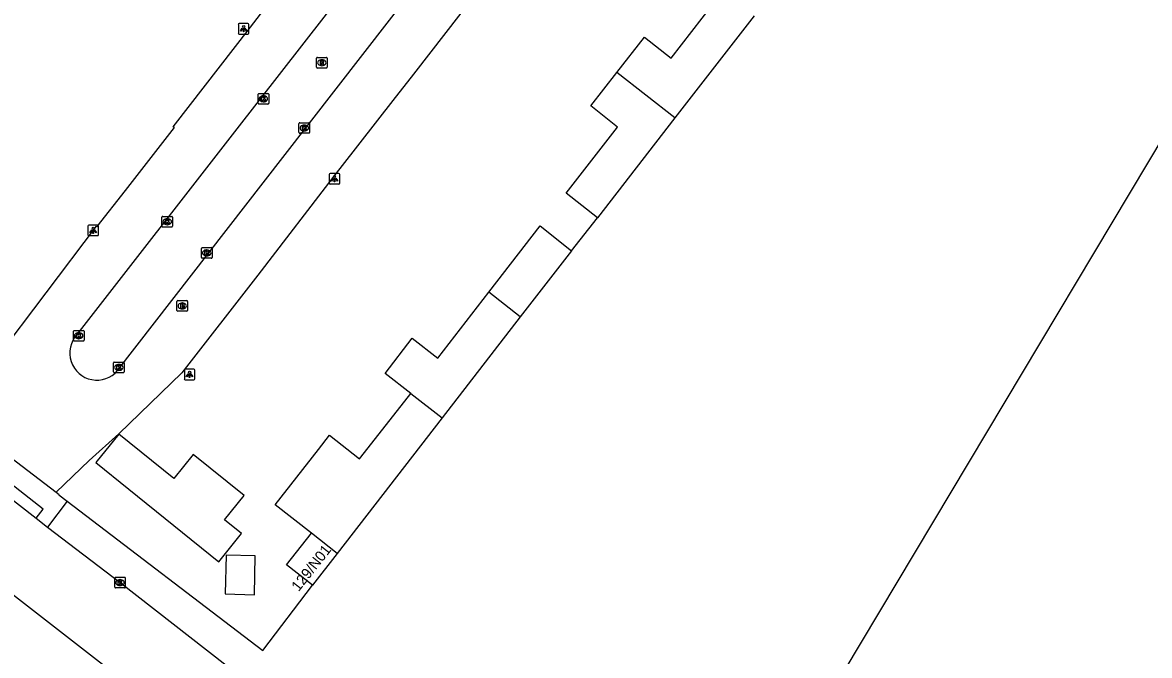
# Model space of a CAD drawing. Extents: x 159451 to 160663, y 388402 to 389723.
# Drawn here: x 160229.1 to 160335.5, y 389285.1 to 389344.8 of the extents above; entities that cross this region are included whole.
import ezdxf

# ---------------------------------------------------------------- set-up
doc = ezdxf.new("R2010")
doc.units = 0
for name, color, linetype in [('IMGEO_Brandkraan', 7, 'Continuous'), ('IMGEO_Groenvoorziening', 7, 'Continuous'), ('IMGEO_Kolk', 7, 'Continuous'), ('IMGEO_Lichtpunt', 7, 'Continuous'), ('IMGEO_Loofbos', 7, 'Continuous'), ('IMGEO_Pand', 7, 'Continuous'), ('IMGEO_Pand_nummerreeks', 7, 'Continuous'), ('IMGEO_Rijbaan_lokaal_gesloten', 7, 'Continuous'), ('IMGEO_Rijbaan_lokaal_open', 7, 'Continuous'), ('IMGEO_Rioolput', 7, 'Continuous')]:
    doc.layers.add(name, color=color, linetype=linetype)

msp = doc.modelspace()

# ---------------------------------------------------------------- linework, layer by layer
at = {"layer": 'IMGEO_Brandkraan'}
for p, q in [((160243.71, 389317.66), (160243.71, 389318.51)), ((160243.79, 389318.59), (160244.64, 389318.59)), ((160244.2, 389318.36), (160244.23, 389318.36)), ((160244.71, 389318.51), (160244.71, 389317.66)), ((160244.64, 389317.58), (160243.79, 389317.58)), ((160244.22, 389317.81), (160244.2, 389317.81))]:
    msp.add_line(p, q, dxfattribs=at)
for points in [[(160243.71, 389317.66), (160243.71, 389318.51)], [(160243.79, 389318.59), (160244.64, 389318.59)], [(160244.06, 389318.28), (160244.06, 389317.88), (160244.27, 389317.88)], [(160244.29, 389318.28), (160244.06, 389318.28)], [(160244.24, 389318.2), (160244.19, 389318.2), (160244.19, 389318.13)], [(160244.19, 389318.13), (160244.24, 389318.13)], [(160244.25, 389318.05), (160244.19, 389318.05), (160244.19, 389317.97)], [(160244.19, 389317.97), (160244.25, 389317.97)], [(160244.71, 389318.51), (160244.71, 389317.66)], [(160244.64, 389317.58), (160243.79, 389317.58)]]:
    msp.add_lwpolyline(points, dxfattribs=at)
for centre, radius, start, end in [((160243.79, 389318.51), 0.0765, 91.552, 178.448), ((160243.79, 389318.51), 0.0765, 91.552, 178.448), ((160244.24, 389318.17), 0.0379, 267.8285, 90.9355), ((160244.25, 389318.01), 0.0404, 269.8759, 90.5077), ((160244.28, 389318.14), 0.251, 268.6676, 293.5347), ((160244.3, 389318.14), 0.145, 59.4692, 91.5367), ((160244.32, 389318.19), 0.0922, 285.5137, 58.1501), ((160244.33, 389318), 0.105, 301.3115, 78.989), ((160244.64, 389318.51), 0.0765, 1.552, 88.448), ((160244.64, 389318.51), 0.0765, 1.552, 88.448), ((160243.79, 389317.66), 0.0765, 181.552, 268.448), ((160243.79, 389317.66), 0.0765, 181.552, 268.448), ((160244.64, 389317.66), 0.0765, 271.552, 358.448), ((160244.64, 389317.66), 0.0765, 271.552, 358.448)]:
    msp.add_arc(centre, radius, start, end, dxfattribs=at)
for centre, major_axis, ratio, start_param, end_param in [((160244.2, 389318.08), (-0.387, 0.002), 0.722429, 4.712389, 7.853982), ((160244.22, 389318.08), (-0.39, 0.002), 0.717154, 1.570796, 4.712389)]:
    msp.add_ellipse(centre, major_axis=major_axis, ratio=ratio, start_param=start_param, end_param=end_param, dxfattribs=at)
at = {"layer": 'IMGEO_Groenvoorziening'}
for points in [[(160280.95, 389323.29), (160283.42, 389326.4)], [(160233.35, 389299.67), (160251.82, 389285.59), (160256.51, 389291.74)]]:
    msp.add_lwpolyline(points, dxfattribs=at)
at = {"layer": 'IMGEO_Kolk'}
for p, q in [((160251.45, 389338.11), (160252.3, 389338.11)), ((160251.37, 389337.18), (160251.37, 389338.04)), ((160252.3, 389337.11), (160251.45, 389337.11)), ((160251.86, 389337.89), (160251.88, 389337.89)), ((160251.88, 389337.33), (160251.86, 389337.33)), ((160252.37, 389338.04), (160252.37, 389337.18)), ((160255.23, 389334.43), (160255.23, 389335.28)), ((160255.3, 389335.36), (160256.16, 389335.36)), ((160255.72, 389335.14), (160255.74, 389335.14)), ((160256.23, 389335.28), (160256.23, 389334.43)), ((160256.16, 389334.36), (160255.3, 389334.36)), ((160255.74, 389334.58), (160255.71, 389334.58)), ((160242.3, 389325.6), (160242.3, 389326.45)), ((160242.37, 389326.52), (160243.22, 389326.52)), ((160243.3, 389326.45), (160243.3, 389325.6)), ((160243.22, 389325.52), (160242.37, 389325.52)), ((160242.78, 389326.3), (160242.81, 389326.3)), ((160242.81, 389325.74), (160242.78, 389325.74)), ((160246.02, 389322.65), (160246.02, 389323.5)), ((160246.1, 389323.58), (160246.95, 389323.58)), ((160246.51, 389323.36), (160246.54, 389323.36)), ((160247.03, 389323.5), (160247.03, 389322.65)), ((160246.95, 389322.58), (160246.1, 389322.58)), ((160246.53, 389322.8), (160246.51, 389322.8)), ((160234.02, 389315.77), (160234.87, 389315.77)), ((160233.94, 389314.84), (160233.94, 389315.7)), ((160234.87, 389314.77), (160234.02, 389314.77)), ((160234.43, 389315.55), (160234.45, 389315.55)), ((160234.45, 389314.99), (160234.43, 389314.99)), ((160234.94, 389315.7), (160234.94, 389314.84)), ((160237.73, 389311.86), (160237.73, 389312.71)), ((160237.8, 389312.78), (160238.66, 389312.78)), ((160238.73, 389312.71), (160238.73, 389311.86)), ((160238.66, 389311.78), (160237.8, 389311.78)), ((160238.24, 389312), (160238.21, 389312)), ((160238.22, 389312.56), (160238.24, 389312.56)), ((160237.84, 389291.56), (160237.84, 389292.42)), ((160237.92, 389292.49), (160238.77, 389292.49)), ((160238.84, 389292.42), (160238.84, 389291.56)), ((160238.77, 389291.49), (160237.92, 389291.49)), ((160238.33, 389292.27), (160238.35, 389292.27)), ((160238.35, 389291.71), (160238.33, 389291.71))]:
    msp.add_line(p, q, dxfattribs=at)
for points in [[(160251.45, 389338.11), (160252.3, 389338.11)], [(160251.37, 389337.18), (160251.37, 389338.04)], [(160252.3, 389337.11), (160251.45, 389337.11)], [(160251.69, 389337.81), (160251.82, 389337.81), (160251.82, 389337.66), (160251.94, 389337.81), (160252.11, 389337.81), (160251.96, 389337.66), (160252.12, 389337.41), (160251.96, 389337.41), (160251.88, 389337.58), (160251.82, 389337.51), (160251.82, 389337.41), (160251.69, 389337.41), (160251.69, 389337.81)], [(160252.37, 389338.04), (160252.37, 389337.18)], [(160255.23, 389334.43), (160255.23, 389335.28)], [(160255.3, 389335.36), (160256.16, 389335.36)], [(160255.55, 389335.06), (160255.67, 389335.06), (160255.67, 389334.91), (160255.8, 389335.06), (160255.97, 389335.06), (160255.82, 389334.91), (160255.97, 389334.66), (160255.82, 389334.66), (160255.74, 389334.82), (160255.67, 389334.76), (160255.67, 389334.66), (160255.55, 389334.66), (160255.55, 389335.06)], [(160256.23, 389335.28), (160256.23, 389334.43)], [(160256.16, 389334.36), (160255.3, 389334.36)], [(160242.3, 389325.6), (160242.3, 389326.45)], [(160242.37, 389326.52), (160243.22, 389326.52)], [(160243.3, 389326.45), (160243.3, 389325.6)], [(160243.22, 389325.52), (160242.37, 389325.52)], [(160242.62, 389326.22), (160242.74, 389326.22), (160242.74, 389326.07), (160242.87, 389326.22), (160243.03, 389326.22), (160242.89, 389326.07), (160243.04, 389325.82), (160242.89, 389325.82), (160242.8, 389325.99), (160242.74, 389325.92), (160242.74, 389325.82), (160242.62, 389325.82), (160242.62, 389326.22)], [(160246.02, 389322.65), (160246.02, 389323.5)], [(160246.1, 389323.58), (160246.95, 389323.58)], [(160246.34, 389323.28), (160246.47, 389323.28), (160246.47, 389323.13), (160246.6, 389323.28), (160246.76, 389323.28), (160246.62, 389323.13), (160246.77, 389322.88), (160246.62, 389322.88), (160246.53, 389323.04), (160246.47, 389322.98), (160246.47, 389322.88), (160246.34, 389322.88), (160246.34, 389323.28)], [(160247.03, 389323.5), (160247.03, 389322.65)], [(160246.95, 389322.58), (160246.1, 389322.58)], [(160234.02, 389315.77), (160234.87, 389315.77)], [(160233.94, 389314.84), (160233.94, 389315.7)], [(160234.87, 389314.77), (160234.02, 389314.77)], [(160234.26, 389315.47), (160234.39, 389315.47), (160234.39, 389315.32), (160234.51, 389315.47), (160234.68, 389315.47), (160234.53, 389315.32), (160234.69, 389315.07), (160234.53, 389315.07), (160234.45, 389315.23), (160234.39, 389315.17), (160234.39, 389315.07), (160234.26, 389315.07), (160234.26, 389315.47)], [(160234.94, 389315.7), (160234.94, 389314.84)], [(160237.73, 389311.86), (160237.73, 389312.71)], [(160237.8, 389312.78), (160238.66, 389312.78)], [(160238.73, 389312.71), (160238.73, 389311.86)], [(160238.66, 389311.78), (160237.8, 389311.78)], [(160238.05, 389312.48), (160238.17, 389312.48), (160238.17, 389312.33), (160238.3, 389312.48), (160238.47, 389312.48), (160238.32, 389312.33), (160238.47, 389312.08), (160238.32, 389312.08), (160238.24, 389312.25), (160238.17, 389312.18), (160238.17, 389312.08), (160238.05, 389312.08), (160238.05, 389312.48)], [(160237.84, 389291.56), (160237.84, 389292.42)], [(160237.92, 389292.49), (160238.77, 389292.49)], [(160238.84, 389292.42), (160238.84, 389291.56)], [(160238.77, 389291.49), (160237.92, 389291.49)], [(160238.16, 389292.19), (160238.29, 389292.19), (160238.29, 389292.04), (160238.41, 389292.19), (160238.58, 389292.19), (160238.43, 389292.04), (160238.59, 389291.79), (160238.43, 389291.79), (160238.35, 389291.95), (160238.29, 389291.89), (160238.29, 389291.79), (160238.16, 389291.79), (160238.16, 389292.19)]]:
    msp.add_lwpolyline(points, dxfattribs=at)
for centre, start, end in [((160251.45, 389338.04), 91.552, 178.448), ((160251.45, 389338.04), 91.552, 178.448), ((160252.3, 389338.04), 1.552, 88.448), ((160252.3, 389338.04), 1.552, 88.448), ((160251.45, 389337.19), 181.552, 268.448), ((160251.45, 389337.19), 181.552, 268.448), ((160252.3, 389337.19), 271.552, 358.448), ((160252.3, 389337.19), 271.552, 358.448), ((160255.31, 389335.28), 91.552, 178.448), ((160255.31, 389335.28), 91.552, 178.448), ((160256.15, 389335.28), 1.552, 88.448), ((160256.15, 389335.28), 1.552, 88.448), ((160255.31, 389334.43), 181.552, 268.448), ((160255.31, 389334.43), 181.552, 268.448), ((160256.15, 389334.43), 271.552, 358.448), ((160256.15, 389334.43), 271.552, 358.448), ((160242.37, 389326.45), 91.552, 178.448), ((160242.37, 389326.45), 91.552, 178.448), ((160243.22, 389326.45), 1.552, 88.448), ((160243.22, 389326.45), 1.552, 88.448), ((160242.37, 389325.6), 181.552, 268.448), ((160242.37, 389325.6), 181.552, 268.448), ((160243.22, 389325.6), 271.552, 358.448), ((160243.22, 389325.6), 271.552, 358.448), ((160246.1, 389323.5), 91.552, 178.448), ((160246.1, 389323.5), 91.552, 178.448), ((160246.95, 389323.5), 1.552, 88.448), ((160246.95, 389323.5), 1.552, 88.448), ((160246.1, 389322.65), 181.552, 268.448), ((160246.1, 389322.65), 181.552, 268.448), ((160246.95, 389322.65), 271.552, 358.448), ((160246.95, 389322.65), 271.552, 358.448), ((160234.02, 389315.69), 91.552, 178.448), ((160234.02, 389315.69), 91.552, 178.448), ((160234.87, 389315.69), 1.552, 88.448), ((160234.87, 389315.69), 1.552, 88.448), ((160234.02, 389314.85), 181.552, 268.448), ((160234.02, 389314.85), 181.552, 268.448), ((160234.87, 389314.85), 271.552, 358.448), ((160234.87, 389314.85), 271.552, 358.448), ((160237.8, 389312.71), 91.552, 178.448), ((160237.8, 389312.71), 91.552, 178.448), ((160238.65, 389312.71), 1.552, 88.448), ((160238.65, 389312.71), 1.552, 88.448), ((160237.8, 389311.86), 181.552, 268.448), ((160237.8, 389311.86), 181.552, 268.448), ((160238.65, 389311.86), 271.552, 358.448), ((160238.65, 389311.86), 271.552, 358.448), ((160237.92, 389292.41), 91.552, 178.448), ((160237.92, 389292.41), 91.552, 178.448), ((160238.77, 389292.41), 1.552, 88.448), ((160238.77, 389292.41), 1.552, 88.448), ((160237.92, 389291.56), 181.552, 268.448), ((160237.92, 389291.56), 181.552, 268.448), ((160238.77, 389291.56), 271.552, 358.448), ((160238.77, 389291.56), 271.552, 358.448)]:
    msp.add_arc(centre, 0.0765, start, end, dxfattribs=at)
for centre, major_axis, ratio, start_param, end_param in [((160251.86, 389337.61), (-0.387, 0.002), 0.722429, 4.712389, 7.853982), ((160251.88, 389337.61), (-0.39, 0.002), 0.717154, 1.570796, 4.712389), ((160255.72, 389334.86), (-0.387, 0.002), 0.722429, 4.712389, 7.853982), ((160255.74, 389334.86), (-0.39, 0.002), 0.717154, 1.570796, 4.712389), ((160242.78, 389326.02), (-0.387, 0.002), 0.722429, 4.712389, 7.853982), ((160242.81, 389326.02), (-0.39, 0.002), 0.717154, 1.570796, 4.712389), ((160246.51, 389323.08), (-0.387, 0.002), 0.722429, 4.712389, 7.853982), ((160246.54, 389323.08), (-0.39, 0.002), 0.717154, 1.570796, 4.712389), ((160234.43, 389315.27), (-0.387, 0.002), 0.722429, 4.712389, 7.853982), ((160234.45, 389315.27), (-0.39, 0.002), 0.717154, 1.570796, 4.712389), ((160238.22, 389312.28), (-0.387, 0.002), 0.722429, 4.712389, 7.853982), ((160238.24, 389312.28), (-0.39, 0.002), 0.717154, 1.570796, 4.712389), ((160238.33, 389291.99), (-0.387, 0.002), 0.722429, 4.712389, 7.853982), ((160238.35, 389291.99), (-0.39, 0.002), 0.717154, 1.570796, 4.712389)]:
    msp.add_ellipse(centre, major_axis=major_axis, ratio=ratio, start_param=start_param, end_param=end_param, dxfattribs=at)
at = {"layer": 'IMGEO_Lichtpunt'}
for p, q in [((160249.51, 389344.62), (160249.51, 389343.81)), ((160249.51, 389344.62), (160249.51, 389343.81)), ((160250.41, 389344.71), (160249.6, 389344.71)), ((160250.41, 389344.71), (160249.6, 389344.71)), ((160250.51, 389343.81), (160250.51, 389344.62)), ((160250.51, 389343.81), (160250.51, 389344.62)), ((160249.6, 389343.72), (160250.41, 389343.72)), ((160249.6, 389343.72), (160250.41, 389343.72)), ((160258.09, 389330.48), (160258.09, 389329.67)), ((160258.09, 389330.48), (160258.09, 389329.67)), ((160258.99, 389330.57), (160258.18, 389330.57)), ((160258.99, 389330.57), (160258.18, 389330.57)), ((160259.09, 389329.67), (160259.09, 389330.48)), ((160259.09, 389329.67), (160259.09, 389330.48)), ((160258.18, 389329.58), (160258.99, 389329.58)), ((160258.18, 389329.58), (160258.99, 389329.58)), ((160235.31, 389325.61), (160235.31, 389324.8)), ((160235.31, 389325.61), (160235.31, 389324.8)), ((160236.21, 389325.71), (160235.4, 389325.71)), ((160236.21, 389325.71), (160235.4, 389325.71)), ((160236.3, 389324.8), (160236.3, 389325.61)), ((160236.3, 389324.8), (160236.3, 389325.61)), ((160235.4, 389324.71), (160236.21, 389324.71)), ((160235.4, 389324.71), (160236.21, 389324.71)), ((160244.41, 389312.03), (160244.41, 389311.22)), ((160244.41, 389312.03), (160244.41, 389311.22)), ((160245.31, 389312.12), (160244.5, 389312.12)), ((160245.31, 389312.12), (160244.5, 389312.12)), ((160245.4, 389311.22), (160245.4, 389312.03)), ((160245.4, 389311.22), (160245.4, 389312.03)), ((160244.5, 389311.12), (160245.31, 389311.12)), ((160244.5, 389311.12), (160245.31, 389311.12))]:
    msp.add_line(p, q, dxfattribs=at)
for points in [[(160249.88, 389344.28), (160249.92, 389344.25), (160249.74, 389343.99), (160249.7, 389344.02), (160249.88, 389344.28)], [(160249.99, 389344.23), (160250.03, 389344.23), (160250.03, 389343.91), (160249.99, 389343.91), (160249.99, 389344.23)], [(160250.1, 389344.25), (160250.13, 389344.28), (160250.32, 389344.02), (160250.28, 389343.99), (160250.1, 389344.25)], [(160258.46, 389330.14), (160258.5, 389330.12), (160258.31, 389329.85), (160258.28, 389329.88), (160258.46, 389330.14)], [(160258.56, 389330.1), (160258.61, 389330.1), (160258.61, 389329.77), (160258.56, 389329.77), (160258.56, 389330.1)], [(160258.67, 389330.12), (160258.71, 389330.14), (160258.9, 389329.88), (160258.86, 389329.85), (160258.67, 389330.12)], [(160235.68, 389325.27), (160235.72, 389325.25), (160235.53, 389324.98), (160235.49, 389325.01), (160235.68, 389325.27)], [(160235.78, 389325.23), (160235.83, 389325.23), (160235.83, 389324.9), (160235.78, 389324.9), (160235.78, 389325.23)], [(160235.89, 389325.25), (160235.93, 389325.27), (160236.12, 389325.01), (160236.08, 389324.98), (160235.89, 389325.25)], [(160244.78, 389311.69), (160244.82, 389311.66), (160244.63, 389311.4), (160244.59, 389311.43), (160244.78, 389311.69)], [(160244.88, 389311.64), (160244.93, 389311.64), (160244.93, 389311.32), (160244.88, 389311.32), (160244.88, 389311.64)], [(160244.99, 389311.66), (160245.03, 389311.69), (160245.22, 389311.43), (160245.18, 389311.4), (160244.99, 389311.66)]]:
    msp.add_lwpolyline(points, dxfattribs=at)
for centre in [(160250.01, 389344.42), (160258.59, 389330.28), (160235.81, 389325.41), (160244.91, 389311.82)]:
    msp.add_circle(centre, 0.0994, dxfattribs=at)
for centre, start, end in [((160249.6, 389344.62), 90, 180), ((160249.6, 389344.62), 90, 180), ((160250.41, 389344.62), 0, 90), ((160250.41, 389344.62), 0, 90), ((160249.6, 389343.81), 180, 270), ((160249.6, 389343.81), 180, 270), ((160250.41, 389343.81), 270, 0), ((160250.41, 389343.81), 270, 360), ((160258.18, 389330.48), 90, 180), ((160258.18, 389330.48), 90, 180), ((160258.18, 389329.67), 180, 270), ((160258.18, 389329.67), 180, 270), ((160258.99, 389330.48), 0, 90), ((160258.99, 389330.48), 0, 90), ((160258.99, 389329.67), 270, 0), ((160258.99, 389329.67), 270, 360), ((160235.4, 389325.61), 90, 180), ((160235.4, 389325.61), 90, 180), ((160236.21, 389325.61), 0, 90), ((160236.21, 389325.61), 0, 90), ((160235.4, 389324.8), 180, 270), ((160235.4, 389324.8), 180, 270), ((160236.21, 389324.8), 270, 0), ((160236.21, 389324.8), 270, 360), ((160244.5, 389312.03), 90, 180), ((160244.5, 389312.03), 90, 180), ((160245.31, 389312.03), 0, 90), ((160245.31, 389312.03), 0, 90), ((160244.5, 389311.22), 180, 270), ((160244.5, 389311.22), 180, 270), ((160245.31, 389311.22), 270, 0), ((160245.31, 389311.22), 270, 360)]:
    msp.add_arc(centre, 0.0946, start, end, dxfattribs=at)
at = {"layer": 'IMGEO_Loofbos'}
msp.add_lwpolyline([(160398.61, 389438.15), (160370.8, 389390.89), (160296.48, 389266.59), (160288.23, 389252.93)], dxfattribs=at)
at = {"layer": 'IMGEO_Pand'}
for points in [[(160285.24, 389340.1), (160287.83, 389343.41), (160290.35, 389341.44), (160295.25, 389347.76)], [(160298.19, 389345.44), (160290.72, 389335.81)], [(160283.42, 389326.4), (160280.45, 389328.72), (160285.31, 389334.95), (160282.77, 389336.94), (160285.24, 389340.1)], [(160290.72, 389335.81), (160285.24, 389340.1)], [(160290.72, 389335.81), (160283.42, 389326.4)], [(160273.16, 389319.38), (160278, 389325.64), (160280.95, 389323.29)], [(160280.95, 389323.29), (160276.11, 389317.05)], [(160265.8, 389309.83), (160263.36, 389311.72), (160265.9, 389315.03), (160268.34, 389313.14), (160273.16, 389319.38)], [(160276.11, 389317.05), (160273.16, 389319.38)], [(160276.11, 389317.05), (160268.75, 389307.54)], [(160256.4, 389296.66), (160252.99, 389299.33), (160257.07, 389304.55), (160258.12, 389305.89), (160260.95, 389303.67), (160265.23, 389309.1), (160265.8, 389309.83)], [(160265.8, 389309.83), (160268.75, 389307.54)], [(160268.75, 389307.54), (160258.84, 389294.75)], [(160245.25, 389304.08), (160243.41, 389301.8), (160238.23, 389305.99), (160236.07, 389303.32), (160239.17, 389300.81), (160247.65, 389293.94), (160249.81, 389296.62), (160248.21, 389297.92), (160250.05, 389300.19), (160245.25, 389304.08)], [(160256.51, 389291.74), (160254.06, 389293.67), (160256.4, 389296.66)], [(160258.84, 389294.75), (160256.4, 389296.66)], [(160248.25, 389290.92), (160251.02, 389290.85), (160251.11, 389294.52), (160248.35, 389294.59), (160248.25, 389290.92)], [(160258.84, 389294.75), (160256.51, 389291.74)]]:
    msp.add_lwpolyline(points, dxfattribs=at)
at = {"layer": 'IMGEO_Rijbaan_lokaal_gesloten'}
for points in [[(160221.68, 389304.85), (160230.42, 389298.07)], [(160230.42, 389298.07), (160231.48, 389297.23)], [(160231.48, 389297.23), (160238.34, 389291.99), (160261.52, 389273.97)], [(160257.09, 389268.4), (160221.21, 389296.26)]]:
    msp.add_lwpolyline(points, dxfattribs=at)
at = {"layer": 'IMGEO_Rijbaan_lokaal_open'}
for points in [[(160226.58, 389313.02), (160236.11, 389325.61), (160236.18, 389325.56), (160238.85, 389328.97), (160243.48, 389334.89), (160243.37, 389334.98), (160250.65, 389344.36), (160255.58, 389350.8), (160257.91, 389353.81), (160265.57, 389363.38), (160266.34, 389364.41), (160268.89, 389367.73), (160272.43, 389372.3), (160272.91, 389372.91), (160280.15, 389382.15), (160280.3, 389382.03), (160280.39, 389382.14), (160280.91, 389381.73), (160288.21, 389390.94), (160290.9, 389388.78), (160291.12, 389388.6)], [(160287.25, 389383.41), (160269.99, 389361.27), (160249.36, 389334.78), (160234.27, 389315.37)], [(160296.57, 389382.44), (160286.53, 389369.74), (160288.25, 389368.42), (160280.8, 389359), (160273.34, 389349.35), (160266.03, 389339.93), (160264.1, 389337.46), (160259.3, 389331.31), (160258.74, 389330.6), (160251.36, 389320.99), (160244.16, 389311.78), (160238.24, 389306.03), (160235.43, 389303.49), (160232.31, 389300.51)], [(160253.7, 389332.09), (160263.77, 389345.01), (160291.24, 389380.3)], [(160238.11, 389311.98), (160253.7, 389332.09)], [(160230.42, 389298.07), (160231.1, 389298.92), (160225.33, 389303.41), (160226.41, 389305), (160232.31, 389300.51)], [(160232.31, 389300.51), (160232.59, 389300.3), (160232.56, 389300.27), (160233.35, 389299.67)], [(160233.35, 389299.67), (160231.48, 389297.23)]]:
    msp.add_lwpolyline(points, dxfattribs=at)
msp.add_arc((160236.16, 389313.64), 2.56, 137.5819, 319.6251, dxfattribs=at)
at = {"layer": 'IMGEO_Rioolput'}
for p, q in [((160256.89, 389340.59), (160256.89, 389341.44)), ((160256.97, 389341.51), (160257.82, 389341.51)), ((160257.38, 389341.29), (160257.4, 389341.29)), ((160257.89, 389341.44), (160257.89, 389340.59)), ((160257.82, 389340.51), (160256.97, 389340.51)), ((160257.4, 389340.73), (160257.38, 389340.73))]:
    msp.add_line(p, q, dxfattribs=at)
for points in [[(160256.89, 389340.59), (160256.89, 389341.44)], [(160256.97, 389341.51), (160257.82, 389341.51)], [(160257.89, 389341.44), (160257.89, 389340.59)], [(160257.82, 389340.51), (160256.97, 389340.51)], [(160257.48, 389341.21), (160257.23, 389341.21), (160257.23, 389340.81)], [(160257.23, 389340.81), (160257.35, 389340.81), (160257.35, 389340.98), (160257.36, 389340.98)], [(160257.41, 389341.13), (160257.35, 389341.13), (160257.35, 389341.05)], [(160257.35, 389341.05), (160257.4, 389341.05)], [(160257.41, 389340.95), (160257.48, 389340.81), (160257.62, 389340.81), (160257.56, 389340.94)]]:
    msp.add_lwpolyline(points, dxfattribs=at)
for centre, radius, start, end in [((160256.97, 389341.44), 0.0765, 91.552, 178.448), ((160256.97, 389341.44), 0.0765, 91.552, 178.448), ((160257.82, 389341.44), 0.0765, 1.552, 88.448), ((160257.82, 389341.44), 0.0765, 1.552, 88.448), ((160256.97, 389340.59), 0.0765, 181.552, 268.448), ((160256.97, 389340.59), 0.0765, 181.552, 268.448), ((160257.36, 389340.92), 0.0533, 26.0293, 88.6989), ((160257.39, 389341.24), 0.19, 274.7715, 282.9687), ((160257.41, 389341.04), 0.0964, 77.0061, 93.1865), ((160257.43, 389341.09), 0.0378, 276.6634, 79.6772), ((160257.48, 389341.1), 0.109, 350.3612, 89.416), ((160257.48, 389341.1), 0.112, 277.5842, 350.9817), ((160257.46, 389340.89), 0.108, 29.5134, 73.7905), ((160257.82, 389340.59), 0.0765, 271.552, 358.448), ((160257.82, 389340.59), 0.0765, 271.552, 358.448)]:
    msp.add_arc(centre, radius, start, end, dxfattribs=at)
for centre, major_axis, ratio, start_param, end_param in [((160257.38, 389341.01), (-0.387, 0.002), 0.722429, 4.712389, 7.853982), ((160257.4, 389341.01), (-0.39, 0.002), 0.717154, 1.570796, 4.712389)]:
    msp.add_ellipse(centre, major_axis=major_axis, ratio=ratio, start_param=start_param, end_param=end_param, dxfattribs=at)

# ---------------------------------------------------------------- texts
at = {"layer": 'IMGEO_Pand_nummerreeks'}
msp.add_text('129/N01', height=1, rotation=51.761, dxfattribs=at).set_placement((160255.2, 389291.09))

doc.saveas('drawing.dxf')
